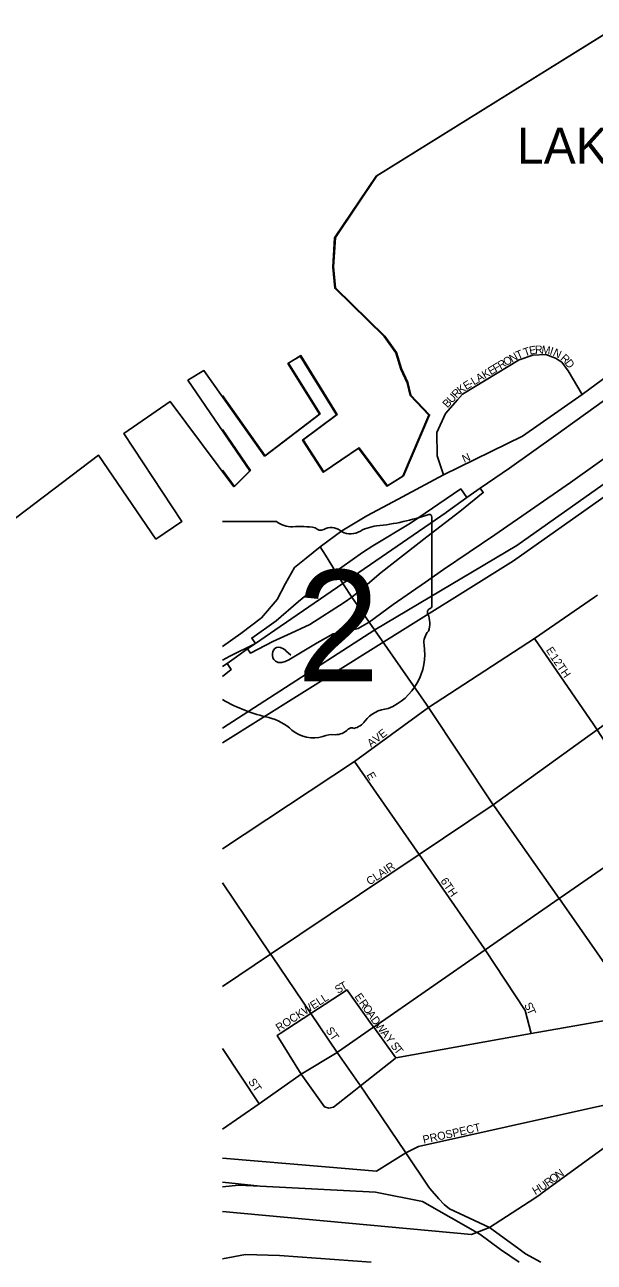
# Model space of a CAD drawing. Extents: x 2139079 to 2262683, y 1235796 to 1334992.
# Drawn here: x 2187563 to 2191123, y 1274636 to 1282370 of the extents above; entities that cross this region are included whole.
import ezdxf

# ---------------------------------------------------------------- set-up
doc = ezdxf.new("R2010")
doc.units = 0
for name, color, linetype in [('GM_X_Airport_Text_Class_1', 7, 'Continuous'), ('GM_X_City_Street', 7, 'Continuous'), ('GM_X_City_Street_Text', 7, 'Continuous'), ('GM_X_Interchange_Ramps', 7, 'Continuous'), ('GM_X_Interstate_Route', 7, 'Continuous'), ('GM_X_Major_Lake', 7, 'Continuous'), ('GM_X_Major_River', 7, 'Continuous'), ('GM_X_Rail_Line', 7, 'Continuous'), ('GM_X_State_Location', 7, 'Continuous'), ('GM_X_State_Route', 7, 'Continuous'), ('GM_X_State_Shield', 7, 'Continuous'), ('GM_X_US_Route', 7, 'Continuous')]:
    doc.layers.add(name, color=color, linetype=linetype)

msp = doc.modelspace()

# ---------------------------------------------------------------- linework, layer by layer
at = {"layer": 'GM_X_City_Street'}
for p, q in [((2189028.5, 1275626.5), (2188798.9, 1275971)), ((2188798.9, 1275287.5), (2189443.4, 1275232.5))]:
    msp.add_line(p, q, dxfattribs=at)
for points in [[(2191381.7, 1280304.3), (2191048.3, 1280060), (2190673.8, 1279798.9), (2190181.3, 1279556.2), (2189865.3, 1279388.6), (2189700.4, 1279301), (2189545.6, 1279207.1), (2189410.1, 1279108)], [(2191048.3, 1280060), (2190960.6, 1280206.3), (2190919.6, 1280261.8), (2190881.6, 1280286.7), (2190820.2, 1280310.1), (2190738.3, 1280305.7), (2190653.5, 1280275), (2190299.5, 1280060.3), (2190269.2, 1280026.4)], [(2190269.2, 1280026.4), (2190193, 1279941.1), (2190139.9, 1279822.1), (2190141.2, 1279676.2), (2190181.3, 1279556.2)], [(2190067.4, 1278886.8), (2190180.5, 1278965), (2190501.9, 1279181.6), (2190975, 1279508.2), (2191475.2, 1279865.9)], [(2188798.9, 1278484.2), (2188914.5, 1278565.2), (2189042.2, 1278663.7), (2189140.8, 1278779), (2189192.1, 1278877.6), (2189249.1, 1278978.9), (2189322.6, 1279035.9), (2189410.1, 1279108)], [(2189442, 1279056.1), (2189410.1, 1279108)], [(2189555.4, 1278871.8), (2189551.7, 1278877.6), (2189505.8, 1278952.2), (2189442, 1279056.1)], [(2189671.6, 1278611.8), (2189716.1, 1278636.6), (2189865.3, 1278747), (2190067.4, 1278886.8)], [(2188798.9, 1277219.2), (2189624.1, 1277765.3), (2190085.9, 1278103.7), (2190750.5, 1278535.1), (2191125.4, 1278793.1), (2191143.3, 1278804.7)], [(2189607.5, 1278793), (2189555.4, 1278871.8)], [(2190073.7, 1278121.3), (2189716.1, 1278636.6), (2189607.5, 1278793)], [(2189226.5, 1278430.5), (2189195.8, 1278458.2), (2189195.6, 1278458.4), (2189180, 1278470.1), (2189162.5, 1278478), (2189150.1, 1278479.2), (2189136.7, 1278477), (2189125.8, 1278470.8), (2189118.1, 1278460.5), (2189113.5, 1278450), (2189111.9, 1278439.8), (2189111.6, 1278428.6), (2189114.7, 1278414.3), (2189121, 1278402.4), (2189130.6, 1278391.6), (2189147.2, 1278385.2), (2189169.2, 1278384.8), (2189190.3, 1278390.4), (2189213.4, 1278401.8), (2189390.3, 1278506.9), (2189442.5, 1278536.8), (2189490.2, 1278562.4), (2189571.4, 1278577.7), (2189646.3, 1278597.8), (2189671.6, 1278611.8)], [(2189005.5, 1278502.9), (2188844.6, 1278423.8), (2188798.9, 1278398.6)], [(2190750.5, 1278535.1), (2191120.8, 1277994)], [(2191083.8, 1277921.3), (2191141.9, 1277963.2), (2191259.9, 1278048.2), (2191327.4, 1278112.6), (2191387, 1278182.8), (2191484.2, 1278250.3)], [(2190499.9, 1277484.1), (2190492.2, 1277495.1), (2190085.9, 1278103.7), (2190073.7, 1278121.3)], [(2191120.8, 1277994), (2191141.9, 1277963.2), (2191537.6, 1277352.6)], [(2190492.2, 1277495.1), (2191083.8, 1277921.3)], [(2190436.7, 1276595.5), (2190027.9, 1277184), (2189624.1, 1277765.3)], [(2188798.9, 1276360.4), (2189099.8, 1276562), (2190027.9, 1277184), (2190492.2, 1277495.1)], [(2190911.1, 1276898.6), (2190904.1, 1276908.6), (2190499.9, 1277484.1)], [(2189107.7, 1276550.2), (2189099.8, 1276562), (2188798.9, 1277007.6)], [(2191204.8, 1276480.4), (2190919.6, 1276886.5), (2190911.1, 1276898.6)], [(2190728.9, 1276066.6), (2190692.1, 1276209.9), (2190441.7, 1276588.3), (2190436.7, 1276595.5)], [(2189515.3, 1275946.5), (2189350.7, 1276190.2), (2189107.7, 1276550.2)], [(2189584.6, 1276328.2), (2189577.6, 1276337.9), (2189350.7, 1276190.2), (2189159.1, 1276065.5)], [(2189733.7, 1276120.4), (2189584.6, 1276328.2)], [(2189882.7, 1275912.6), (2189744.5, 1276105.3), (2189733.7, 1276120.4)], [(2189159.1, 1276065.5), (2189141, 1276053.7), (2189291.6, 1275811.5)], [(2190874.7, 1275548.5), (2191712.1, 1275734.3), (2193043.2, 1275994.2)], [(2190797.8, 1275069.2), (2191712.1, 1275734.3)], [(2189946.1, 1275320.5), (2190023.9, 1275359.7), (2190874.7, 1275548.5)], [(2189443.4, 1275232.5), (2189761.5, 1275205.3), (2189946.1, 1275320.5)], [(2190468.8, 1274853.7), (2190716, 1275014.7)], [(2190716, 1275014.7), (2190782, 1275057.7), (2190797.8, 1275069.2)], [(2188798.9, 1274953.9), (2190356.4, 1274808.7), (2190468.8, 1274853.7)], [(2188798.9, 1274657.9), (2188943.7, 1274685.5), (2189155.9, 1274678.2), (2189727.9, 1274636.1)]]:
    msp.add_lwpolyline(points, dxfattribs=at)
at = {"layer": 'GM_X_Interchange_Ramps'}
for points in [[(2190327.4, 1279415.7), (2190288.9, 1279469.2), (2189974.8, 1279255.2), (2189738.5, 1279113.7), (2189674.8, 1279072.2), (2189544.8, 1278979.2), (2189505.8, 1278952.2)], [(2189607.5, 1278793), (2189661.9, 1278837.1), (2189791.7, 1278946.5), (2190077.3, 1279170.2), (2190282, 1279328), (2190428.8, 1279445.7), (2190409.6, 1279474)], [(2189505.8, 1278952.2), (2189466.7, 1278921), (2189274.6, 1278764.6), (2189133.8, 1278644.7), (2188982.1, 1278536.5), (2189005.5, 1278502.9)], [(2188956.4, 1278468.7), (2188973.9, 1278443.5), (2189114.3, 1278516.1), (2189227.5, 1278568), (2189345.1, 1278622.7), (2189559.6, 1278759.3), (2189607.5, 1278793)], [(2188798.9, 1278296.7), (2188852.9, 1278339.6), (2188829, 1278378.3)]]:
    msp.add_lwpolyline(points, dxfattribs=at)
at = {"layer": 'GM_X_Interstate_Route'}
msp.add_lwpolyline([(2186776.1, 1278733.6), (2188023, 1279680.2), (2188382.4, 1279155.6), (2188545.1, 1279266.5), (2188181.3, 1279815.1), (2188471.1, 1280016.3), (2188870.7, 1279482.2), (2188969.4, 1279582.1), (2188583.3, 1280148.5), (2188682.7, 1280208.3), (2189062.3, 1279673.9), (2189405.2, 1279936.1), (2189207.6, 1280252.4), (2189285.1, 1280299.7), (2189511.6, 1279931.7), (2189299.4, 1279773.9), (2189429, 1279573), (2189649.3, 1279723), (2189825.6, 1279486.7), (2189926.9, 1279548.4), (2190089.4, 1279930.4), (2189973.1, 1280053.2), (2189953.8, 1280131.2), (2189914.3, 1280216.9), (2189882.6, 1280318.8), (2189808.8, 1280422.1), (2189501.1, 1280722.7), (2189488.9, 1280855), (2189500.1, 1281037.9), (2189760.3, 1281423.6), (2195942.9, 1285269.6)], dxfattribs=at)
at = {"layer": 'GM_X_Major_Lake'}
for points in [[(2189764.7, 1281426.2), (2195947.3, 1285272.1), (2196057.6, 1285267), (2196083.9, 1285284.2)], [(2188798.9, 1280053.3), (2189066.6, 1279676.4), (2189409.6, 1279938.7), (2189212, 1280254.9), (2189289.5, 1280302.3), (2189516, 1279934.3), (2189303.8, 1279776.4), (2189433.4, 1279575.6), (2189653.7, 1279725.5), (2189830, 1279489.2), (2189931.3, 1279551), (2190093.8, 1279933), (2189977.5, 1280055.7), (2189958.2, 1280133.7), (2189918.7, 1280219.5), (2189887, 1280321.4), (2189813.1, 1280424.7), (2189505.5, 1280725.2), (2189493.3, 1280857.6), (2189504.5, 1281040.5), (2189764.7, 1281426.2)], [(2188798.9, 1280053.3), (2189066.6, 1279676.4), (2189409.6, 1279938.7), (2189212, 1280254.9), (2189289.5, 1280302.3), (2189516, 1279934.3), (2189303.8, 1279776.4), (2189433.4, 1279575.6), (2189653.7, 1279725.5), (2189830, 1279489.2), (2189931.3, 1279551), (2190093.8, 1279933), (2189977.5, 1280055.7), (2189958.2, 1280133.7), (2189918.7, 1280219.5), (2189887, 1280321.4), (2189813.1, 1280424.7), (2189505.5, 1280725.2), (2189493.3, 1280857.6), (2189504.5, 1281040.5), (2189764.7, 1281426.2)], [(2188798.9, 1279586.6), (2188875.1, 1279484.8), (2188973.8, 1279584.7), (2188798.9, 1279841.2)], [(2188798.9, 1279586.6), (2188875.1, 1279484.8), (2188973.8, 1279584.7), (2188798.9, 1279841.2)]]:
    msp.add_lwpolyline(points, dxfattribs=at)
at = {"layer": 'GM_X_Major_River'}
for points in [[(2188798.9, 1280053.3), (2189066.6, 1279676.4), (2189409.6, 1279938.7), (2189212, 1280254.9), (2189289.5, 1280302.3), (2189516, 1279934.3), (2189303.8, 1279776.4), (2189433.4, 1279575.6), (2189653.7, 1279725.5), (2189830, 1279489.2), (2189931.3, 1279551), (2190093.8, 1279933), (2189977.5, 1280055.7), (2189958.2, 1280133.7), (2189918.7, 1280219.5), (2189887, 1280321.4), (2189813.1, 1280424.7), (2189505.5, 1280725.2), (2189493.3, 1280857.6), (2189504.5, 1281040.5), (2189764.7, 1281426.2)], [(2188798.9, 1279586.6), (2188875.1, 1279484.8), (2188973.8, 1279584.7), (2188798.9, 1279841.2)]]:
    msp.add_lwpolyline(points, dxfattribs=at)
at = {"layer": 'GM_X_Rail_Line'}
msp.add_line((2188798.9, 1275137.6), (2189034, 1275111), dxfattribs=at)
for points in [[(2188798.9, 1277974.5), (2189752.1, 1278588.8), (2190639.6, 1279116), (2192678, 1280555.1), (2194231.5, 1281639.3), (2194948.6, 1282154.6), (2195509, 1282554.5), (2195871.7, 1282810.1), (2196378.5, 1283156.3), (2197087.3, 1283630.4), (2199383.9, 1285076.5), (2199860.7, 1285394.8)], [(2188798.9, 1277881.4), (2189757.9, 1278481.3), (2190617.3, 1279020.4), (2191767.2, 1279829.6), (2191989.8, 1279978), (2192129.9, 1280056.3), (2192326.4, 1280152.7), (2192459.3, 1280209.9), (2192568.2, 1280252.3), (2192695.5, 1280304), (2194123.4, 1280872.7), (2194416.4, 1280986.7)], [(2188798.9, 1275107.7), (2188901.3, 1275117.7), (2189034, 1275111)], [(2190653, 1274636.1), (2190537.9, 1274716.3), (2190408.1, 1274810.8), (2190050.1, 1275015.4), (2189755, 1275074.4), (2189034, 1275111)]]:
    msp.add_lwpolyline(points, dxfattribs=at)
at = {"layer": 'GM_X_State_Route'}
msp.add_line((2188798.9, 1278358.6), (2188829, 1278378.3), dxfattribs=at)
for points in [[(2190881.9, 1279805.4), (2191491, 1280241.7), (2191624.5, 1280348.6), (2191791, 1280496.4), (2192133.4, 1280869.4), (2192373.6, 1281120.4), (2192502.1, 1281240.5), (2192649.6, 1281363.5), (2192834.7, 1281498.8), (2192862.8, 1281519)], [(2190199.6, 1279323.8), (2190327.4, 1279415.7), (2190409.6, 1279474), (2190592.9, 1279598.3), (2190881.9, 1279805.4)], [(2189551.7, 1278877.6), (2190197, 1279321.9), (2190199.6, 1279323.8)], [(2189126.3, 1278585.7), (2189551.7, 1278877.6)], [(2188829, 1278378.3), (2188885.8, 1278419.5), (2188956.4, 1278468.7), (2189005.5, 1278502.9), (2189126.3, 1278585.7)]]:
    msp.add_lwpolyline(points, dxfattribs=at)
at = {"layer": 'GM_X_State_Shield'}
for p, q in [((2189136.6, 1279266.1), (2188798.9, 1279266.1)), ((2190107.4, 1278739.5), (2190107.4, 1279293.2)), ((2190107.3, 1278739.7), (2190107.4, 1278739.5))]:
    msp.add_line(p, q, dxfattribs=at)
for centre, radius, start, end in [((2189233.7, 1279388.7), 156.4, 231.64044, 271.11173), ((2189611.5, 1280706.6), 1476.4, 275.84447, 288.90645), ((2190091.9, 1279294.6), 15.5, 355.09784, 97.73796), ((2189285.6, 1278672.9), 561.6, 80.48669, 94.98831), ((2189413.1, 1279255.6), 45.1, 219.79206, 297.10237), ((2189479.3, 1279133.5), 93.8, 54.46671, 119.14113), ((2189600.4, 1279301), 112.9, 233.85619, 294.82819), ((2189799.8, 1278943.4), 297, 97.3462, 120.76885), ((2190103.8, 1278698.9), 24, 107.94398, 210.33697), ((2190090.9, 1278737.4), 16.6, 289.60381, 7.73413), ((2189951.2, 1278629.1), 144, 340.03296, 23.64957), ((2190162.9, 1278508.2), 104.8, 136.8065, 186.92959), ((2189694.2, 1278437.9), 369.3, 292.30889, 8.98584), ((2189324.5, 1279079.6), 1066.1, 240.46662, 257.1985), ((2189006.6, 1277716.6), 333.6, 47.18415, 75.83597), ((2189849.9, 1277894.6), 202.2, 94.40312, 142.57675), ((2189367.4, 1278125.1), 211.7, 230.70037, 286.29183), ((2189505.2, 1278045.9), 112.8, 268.77705, 315.54927), ((2189607.2, 1277943.6), 31.8, 65.75173, 132.64842), ((2189593.6, 1278088.9), 119.3, 282.87319, 323.27711), ((2189489.7, 1277759.7), 173.9, 85.6951, 111.20996)]:
    msp.add_arc(centre, radius, start, end, dxfattribs=at)
at = {"layer": 'GM_X_US_Route'}
for points in [[(2190916.6, 1276917.3), (2191539.9, 1277349.1), (2191571.8, 1277371.2)], [(2189737.3, 1276100.3), (2189744.5, 1276105.3), (2190441.7, 1276588.3), (2190904.1, 1276908.6), (2190916.6, 1276917.3)], [(2189879.5, 1275910), (2189882.7, 1275912.6), (2190728.9, 1276066.6), (2191406.5, 1276184.9)], [(2189518.9, 1275949), (2189737.3, 1276100.3)], [(2189291.6, 1275811.5), (2189291.6, 1275811.5), (2189515.3, 1275946.5), (2189518.9, 1275949)], [(2189515.3, 1275946.5), (2189661.9, 1275738.3), (2189693.5, 1275691.9)], [(2189620.8, 1275705.8), (2189661.9, 1275738.3), (2189879.5, 1275910)], [(2188798.9, 1275468.4), (2189028.5, 1275626.5), (2189291.6, 1275811.5)], [(2189291.6, 1275811.5), (2189436.5, 1275607.4), (2189463.2, 1275598.3), (2189493.7, 1275605.5), (2189620.8, 1275705.8)], [(2189693.5, 1275691.9), (2189946.1, 1275320.5)], [(2189946.1, 1275320.5), (2190089.6, 1275106.1)], [(2190089.6, 1275106.1), (2190096.2, 1275096.2), (2190150.8, 1275032), (2190184.5, 1274996.7), (2190218.3, 1274969.3), (2190468.8, 1274853.7), (2190643.5, 1274725.7)], [(2190643.5, 1274725.7), (2190693.6, 1274689.1), (2190788.4, 1274636.1)]]:
    msp.add_lwpolyline(points, dxfattribs=at)

# ---------------------------------------------------------------- texts
at = {"layer": 'GM_X_Airport_Text_Class_1'}
msp.add_text('LAKEFRONT', height=225, rotation=0.00001, dxfattribs=at).set_placement((2190639.8, 1281501))
at = {"layer": 'GM_X_City_Street_Text'}
for s, rotation, p in [('T', 19.11732, (2190689.5, 1280297)), ('E', 10.63476, (2190720.9, 1280308)), ('R', 2.30808, (2190753.6, 1280314.3)), ('M', 353.1348, (2190791, 1280316)), ('I', 342.32527, (2190841, 1280310.2)), ('N', 334.70581, (2190860.4, 1280304.1)), ('R', 30.93717, (2190537.3, 1280214.9)), ('O', 30.91877, (2190571.3, 1280235.2)), ('N', 29.73403, (2190608.8, 1280257.7)), ('T', 23.04435, (2190645.6, 1280278.8)), ('R', 317.59399, (2190908, 1280280.5)), ('D', 307.46867, (2190935.7, 1280255.5)), ('A', 30.91877, (2190401.4, 1280133.5)), ('K', 30.926, (2190439.2, 1280156.1)), ('E', 30.93776, (2190476.9, 1280178.7)), ('F', 30.93096, (2190507.1, 1280196.8)), ('K', 36.21859, (2190287.7, 1280060.5)), ('E', 31.18866, (2190322.3, 1280085.9)), ('-', 30.8888, (2190352.3, 1280104.1)), ('L', 30.93209, (2190371.2, 1280115.4)), ('B', 47.54175, (2190206, 1279971.8)), ('U', 47.54984, (2190232.7, 1280001)), ('R', 46.563, (2190262.3, 1280033.3)), ('N', 23.97375, (2190310.4, 1279630.9)), ('E', 303.69848, (2190819.2, 1278461.5)), ('12TH', 304.69647, (2190845.5, 1278417.6)), ('AVE', 38.05088, (2189727.6, 1277852.1)), ('E', 299.75497, (2189697.6, 1277682.2)), ('CLAIR', 33.99394, (2189719.3, 1276990.1)), ('6TH', 304.59353, (2190159.1, 1277018.4)), ('S', 32.7582, (2189521.2, 1276312.4)), ('T', 29.60931, (2189550.2, 1276331.1)), ('ROCKWELL', 32.87032, (2189152, 1276075.1)), ('E', 304.70553, (2189622.3, 1276296.8)), ('R', 304.72741, (2189649.9, 1276257)), ('S', 298.14161, (2190683, 1276243.7)), ('O', 304.71451, (2189672.5, 1276224.5)), ('A', 304.71451, (2189697.5, 1276188.3)), ('D', 305.75922, (2189723.2, 1276151.3)), ('T', 292.395, (2190699, 1276213.9)), ('ST', 304.69866, (2189441.9, 1276085.6)), ('W', 307.72724, (2189750, 1276114.1)), ('A', 307.87444, (2189785.1, 1276068.8)), ('Y', 307.89029, (2189812.1, 1276034)), ('S', 307.8716, (2189847.2, 1275988.8)), ('T', 307.88894, (2189868.9, 1275961.1)), ('ST', 304.69079, (2188957.9, 1275764.4)), ('PROSPECT', 12.61858, (2190056.9, 1275376.7)), ('R', 36.01817, (2190832.9, 1275105.2)), ('O', 36.04952, (2190864.9, 1275128.5)), ('N', 36.03058, (2190900.5, 1275154.4)), ('H', 30.21395, (2190754.3, 1275054.7)), ('U', 35.13325, (2190796.2, 1275079.3))]:
    msp.add_text(s, height=50, rotation=rotation, dxfattribs=at).set_placement(p)
at = {"layer": 'GM_X_State_Location'}
for s in ['s', 'r']:
    msp.add_text(s, height=1, dxfattribs=at).set_placement((2189395.6, 1278649.3))
msp.add_text('2', height=1, rotation=0.00001, dxfattribs=at).set_placement((2189245, 1278576.6))
at = {"layer": 'GM_X_State_Shield'}
msp.add_text('2', height=696.1, dxfattribs=at).set_placement((2189263.3, 1278265.8))

doc.saveas('drawing.dxf')
